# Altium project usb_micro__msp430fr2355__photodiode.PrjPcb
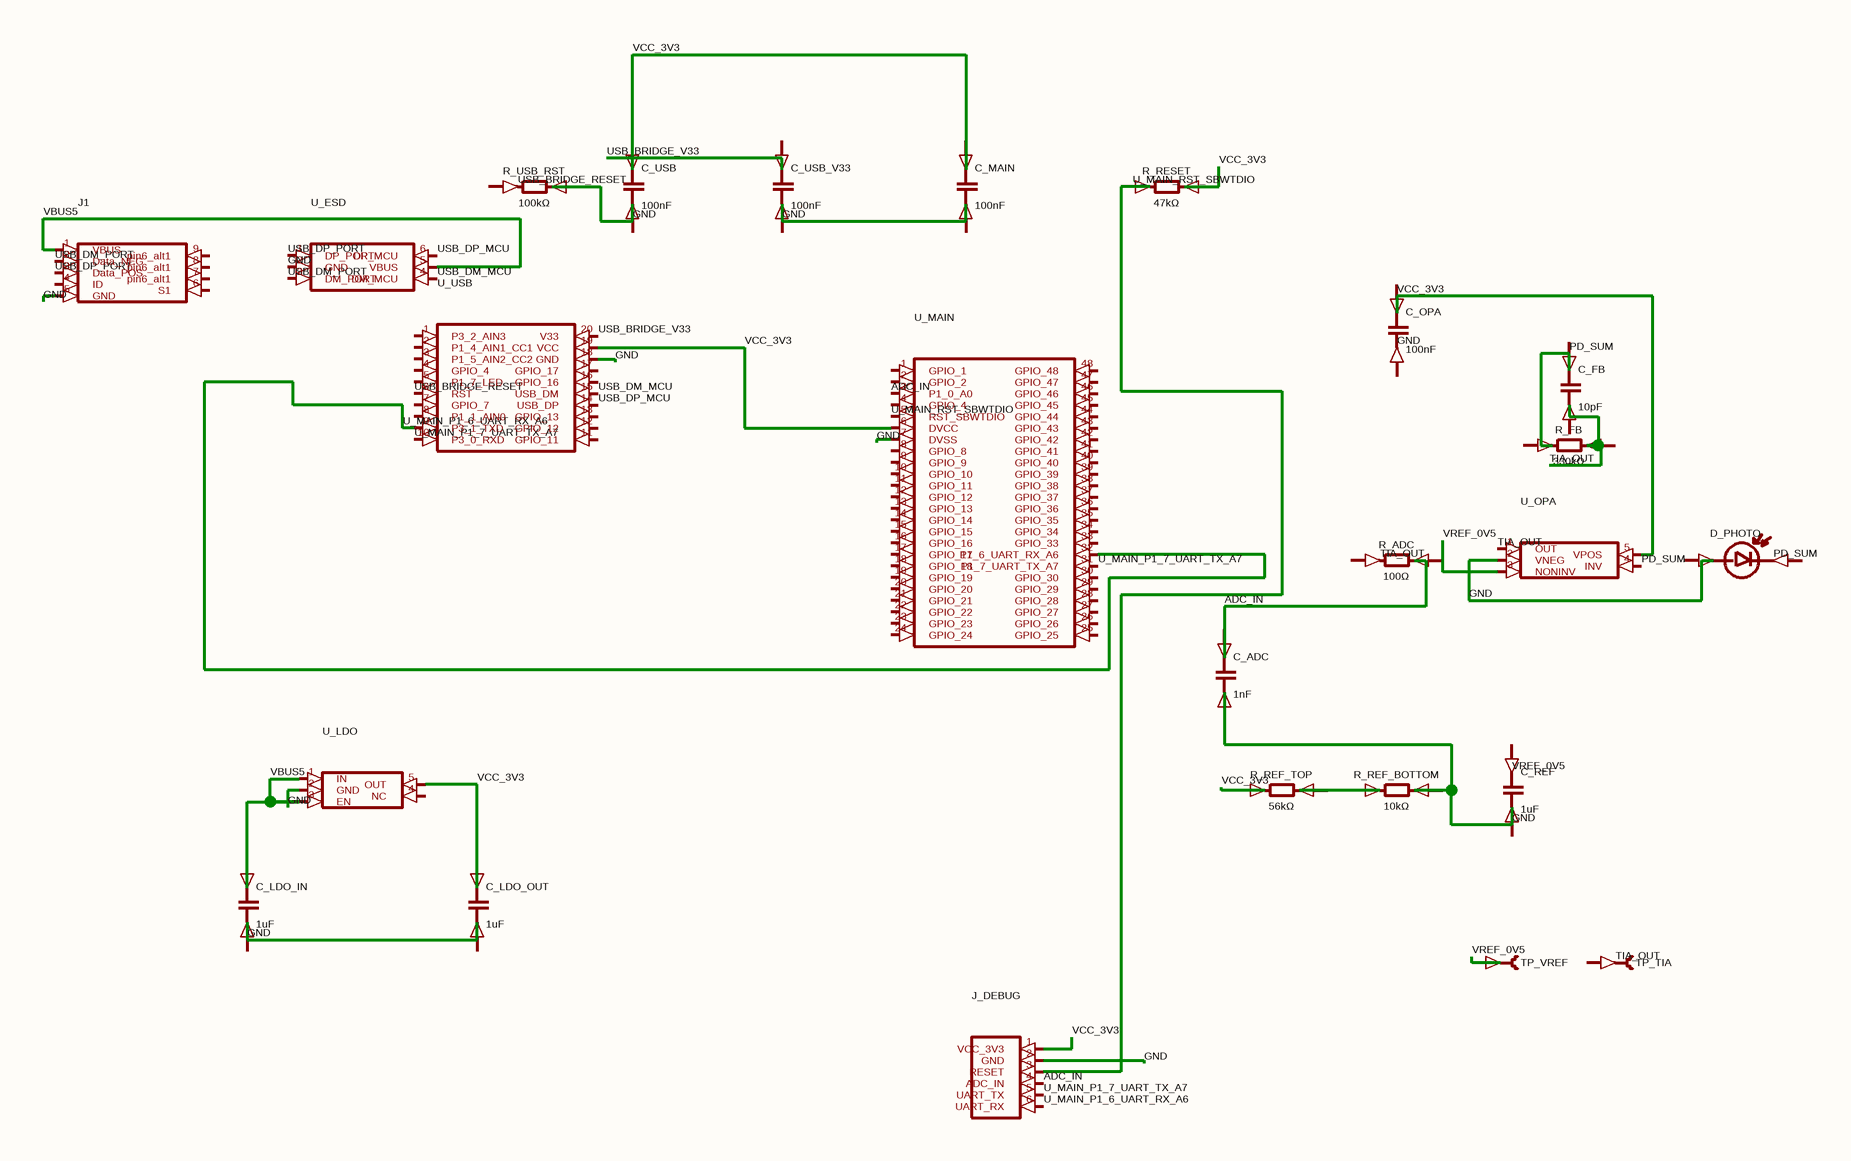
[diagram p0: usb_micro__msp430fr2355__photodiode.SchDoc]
1 sheet, 25 parts. Net scope: global (net labels, ports and power ports of the same name join across sheets).
Board file: usb_micro__msp430fr2355__photodiode.PcbDoc

## Sheet usb_micro__msp430fr2355__photodiode.SchDoc
size 208 x 144 mm

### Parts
C_ADC  1nF
C_FB  10pF
C_LDO_IN  1uF
C_LDO_OUT  1uF
C_MAIN  100nF
C_OPA  100nF
C_REF  1uF
C_USB  100nF
C_USB_V33  100nF
D_PHOTO  (no value)
J1  (no value)
J_DEBUG  (no value)
R_ADC  100Ω
R_FB  330kΩ
R_REF_BOTTOM  10kΩ
R_REF_TOP  56kΩ
R_RESET  47kΩ
R_USB_RST  100kΩ
TP_TIA  (no value)
TP_VREF  (no value)
U_ESD  (no value)
U_LDO  (no value)
U_MAIN  (no value)
U_OPA  (no value)
U_USB  (no value)

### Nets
ADC_IN: C_ADC.1(anode) J_DEBUG.4(ADC_IN) U_MAIN.3(P1_0_A0)
GND: C_ADC.2(cathode) C_LDO_IN.1(anode) J1.1(VBUS) J1.5(GND) J_DEBUG.2(GND) R_REF_BOTTOM.2(cathode) R_USB_RST.2(cathode) U_ESD.2(GND) U_ESD.5(VBUS) U_LDO.1(IN) U_LDO.2(GND) U_LDO.3(EN) U_MAIN.7(DVSS) U_OPA.2(VNEG) U_USB.18(GND)  [also labelled VBUS5]
PD_SUM: U_OPA.4(INV)
TIA_OUT: U_OPA.1(OUT)
U_MAIN_P1_6_UART_RX_A6: J_DEBUG.6(UART_RX) U_MAIN.32(P1_6_UART_RX_A6) U_USB.9(P3_1_TXD)
U_MAIN_P1_7_UART_TX_A7: J_DEBUG.5(UART_TX) U_MAIN.31(P1_7_UART_TX_A7) U_USB.10(P3_0_RXD)
U_MAIN_RST_SBWTDIO: J_DEBUG.3(RESET) R_RESET.1(anode) U_MAIN.5(RST_SBWTDIO)
USB_BRIDGE_RESET: U_USB.6(RST)
USB_BRIDGE_V33: C_LDO_OUT.1(anode) C_MAIN.1(anode) C_USB.1(anode) J_DEBUG.1(VCC_3V3) R_REF_TOP.1(anode) R_RESET.2(cathode) U_LDO.5(OUT) U_MAIN.6(DVCC) U_OPA.5(VPOS) U_USB.19(VCC) U_USB.20(V33)  [also labelled VCC_3V3]
USB_DM_MCU: U_ESD.4(DM_MCU) U_USB.15(USB_DM)
USB_DM_PORT: J1.2(Data_NEG) U_ESD.3(DM_PORT)
USB_DP_MCU: U_ESD.6(DP_MCU) U_USB.14(USB_DP)
USB_DP_PORT: J1.3(Data_POS) U_ESD.1(DP_PORT)
VREF_0V5: R_ADC.2(cathode) TP_VREF.1(pin1) U_OPA.3(NONINV)
NetR_REF_BOTTOM_1: R_REF_BOTTOM.1(anode) R_REF_TOP.2(cathode)

Not connected (* = marked no-connect by the designer): C_FB 1(anode) 2(cathode); C_LDO_IN 2(cathode); C_LDO_OUT 2(cathode); C_MAIN 2(cathode); C_OPA 1(anode) 2(cathode); C_REF 1(anode) 2(cathode); C_USB 2(cathode); C_USB_V33 1(anode) 2(cathode); D_PHOTO 1(anode) 2(cathode); J1 4(ID) 6(S1) 7(pin6_alt1) 8(pin6_alt1) 9(pin6_alt1); R_ADC 1(anode); R_FB 1(anode) 2(cathode); R_USB_RST 1(anode); TP_TIA 1(pin1); U_LDO 4(NC); U_MAIN 1(GPIO_1) 2(GPIO_2) 4(GPIO_4) 8(GPIO_8) 9(GPIO_9) 10(GPIO_10) 11(GPIO_11) 12(GPIO_12) 13(GPIO_13) 14(GPIO_14) 15(GPIO_15) 16(GPIO_16) 17(GPIO_17) 18(GPIO_18) 19(GPIO_19) 20(GPIO_20) 21(GPIO_21) 22(GPIO_22) 23(GPIO_23) 24(GPIO_24) 25(GPIO_25) 26(GPIO_26) 27(GPIO_27) 28(GPIO_28) 29(GPIO_29) 30(GPIO_30) 33(GPIO_33) 34(GPIO_34) 35(GPIO_35) 36(GPIO_36) 37(GPIO_37) 38(GPIO_38) 39(GPIO_39) 40(GPIO_40) 41(GPIO_41) 42(GPIO_42) 43(GPIO_43) 44(GPIO_44) 45(GPIO_45) 46(GPIO_46) 47(GPIO_47) 48(GPIO_48); U_USB 1(P3_2_AIN3) 2(P1_4_AIN1_CC1) 3(P1_5_AIN2_CC2) 4(GPIO_4) 5(P1_7_LED) 7(GPIO_7) 8(P1_1_AIN0) 11(GPIO_11) 12(GPIO_12) 13(GPIO_13) 16(GPIO_16) 17(GPIO_17)

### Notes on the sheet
- Labels drawn without touching a wire or pin: GND, PD_SUM, TIA_OUT, USB_BRIDGE_RESET, VREF_0V5

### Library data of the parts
C_ADC C_FB C_LDO_IN C_LDO_OUT C_MAIN C_OPA C_REF C_USB C_USB_V33 = capacitor_down
D_PHOTO = photodiode_horz
J1 = J1
J_DEBUG = J_DEBUG
R_ADC R_FB R_REF_BOTTOM R_REF_TOP R_RESET R_USB_RST = boxresistor_right
TP_TIA TP_VREF = testpoint_right
U_ESD = U_ESD
U_LDO = U_LDO
U_MAIN = U_MAIN
U_OPA = U_OPA
U_USB = U_USB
